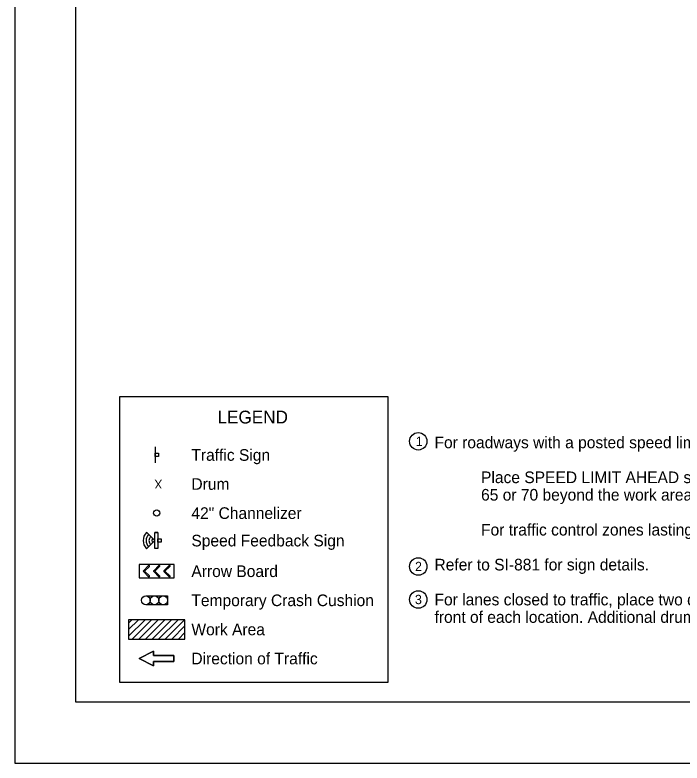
# Model space of a CAD drawing. Extents: x -2135039 to 114557, y -2139150 to -409929.
# Drawn here: x -2131439 to -2130293, y -2139150 to -2137865 of the extents above; entities that cross this region are included whole.
import ezdxf

# ---------------------------------------------------------------- set-up
doc = ezdxf.new("R2010")
doc.units = 0
for name, color, linetype in [('dsnDOTLogo', 7, 'Continuous'), ('dsnStdLabel', 7, 'Continuous'), ('dsnStdLineWork', 7, 'Continuous'), ('dsnStdNote', 7, 'Continuous'), ('Level 1', 7, 'Continuous'), ('Level 2', 7, 'Continuous'), ('StdNote', 7, 'Continuous')]:
    doc.layers.add(name, color=color, linetype=linetype)

msp = doc.modelspace()

# ---------------------------------------------------------------- linework, layer by layer
at = {"layer": 'dsnDOTLogo'}
msp.add_lwpolyline([(-2131438.9, -2139150.4), (-2128095, -2139150.4), (-2128095, -2136566.4), (-2131438.9, -2136566.4)], close=True, dxfattribs=at)
at = {"layer": 'dsnStdLabel'}
for p, q in [((-2131198, -2138607.5), (-2131198, -2138635)), ((-2131193.3, -2138754.5), (-2131193.3, -2138782)), ((-2131218.1, -2138820.1), (-2131209.3, -2138811.3)), ((-2131200.6, -2138820.1), (-2131191.8, -2138811.3)), ((-2131182.9, -2138820.1), (-2131174.1, -2138811.3)), ((-2131214.1, -2138863.4), (-2131176.6, -2138863.4)), ((-2131176.6, -2138863.4), (-2131176.6, -2138878.4)), ((-2131176.6, -2138878.4), (-2131214.1, -2138878.4)), ((-2131243.7, -2138909.9), (-2131238, -2138904.2)), ((-2131243.7, -2138921.2), (-2131226.7, -2138904.2)), ((-2131243.7, -2138932.5), (-2131215.4, -2138904.2)), ((-2131237.4, -2138937.5), (-2131204.1, -2138904.2)), ((-2131226.1, -2138937.5), (-2131192.8, -2138904.2)), ((-2131214.7, -2138937.5), (-2131181.5, -2138904.2)), ((-2131203.4, -2138937.5), (-2131170.1, -2138904.2)), ((-2131192.1, -2138937.5), (-2131158.8, -2138904.2)), ((-2131180.8, -2138937.5), (-2131147.5, -2138904.2)), ((-2131169.5, -2138937.5), (-2131147, -2138915)), ((-2131158.2, -2138937.5), (-2131147, -2138926.4))]:
    msp.add_line(p, q, dxfattribs=at)
for points in [[(-2131197.9, -2138623.9), (-2131197.9, -2138618.3), (-2131192.3, -2138618.3), (-2131192.3, -2138623.9)], [(-2131198.9, -2138782), (-2131198.9, -2138754.5), (-2131193.3, -2138754.5), (-2131193.3, -2138782)], [(-2131193.3, -2138771), (-2131193.3, -2138765.3), (-2131187.7, -2138765.3), (-2131187.7, -2138771)], [(-2131165.4, -2138809.4), (-2131225.4, -2138809.4), (-2131225.4, -2138832.3), (-2131165.4, -2138832.3)], [(-2131243.7, -2138904.2), (-2131243.7, -2138937.5), (-2131147, -2138937.5), (-2131147, -2138904.2)], [(-2131165.7, -2138965.9), (-2131165.7, -2138975.9), (-2131200.7, -2138975.9), (-2131200.7, -2138983.4), (-2131225.7, -2138970.9), (-2131200.7, -2138958.4), (-2131200.7, -2138965.9)]]:
    msp.add_lwpolyline(points, close=True, dxfattribs=at)
for points in [[(-2131209.3, -2138830.4), (-2131209.3, -2138830.4), (-2131218.1, -2138821.6), (-2131218.1, -2138821.6)], [(-2131207.9, -2138812.8), (-2131207.9, -2138812.8), (-2131216.4, -2138820.9), (-2131207.9, -2138828.9)], [(-2131191.8, -2138830.4), (-2131191.8, -2138830.4), (-2131200.6, -2138821.6), (-2131200.6, -2138821.6)], [(-2131190.3, -2138812.8), (-2131190.4, -2138812.8), (-2131198.8, -2138820.9), (-2131190.4, -2138828.9)], [(-2131174.1, -2138830.4), (-2131174.1, -2138830.4), (-2131183, -2138821.6), (-2131183, -2138821.6)], [(-2131172.7, -2138812.8), (-2131172.7, -2138812.8), (-2131181.2, -2138820.9), (-2131172.7, -2138828.9)], [(-2131200.7, -2138965.9), (-2131200.7, -2138958.4), (-2131225.7, -2138970.9), (-2131200.7, -2138983.4), (-2131200.7, -2138975.9), (-2131165.7, -2138975.9), (-2131165.7, -2138965.9), (-2131200.7, -2138965.9)]]:
    msp.add_lwpolyline(points, dxfattribs=at)
for centre, radius in [((-2131195.4, -2138721.1), 5.37), ((-2131195.4, -2138721.1), 5.37), ((-2131214.1, -2138870.9), 7.5), ((-2131214.1, -2138870.9), 7.5), ((-2131199.1, -2138870.9), 7.5), ((-2131199.1, -2138870.9), 7.5), ((-2131184.1, -2138870.9), 7.5), ((-2131184.1, -2138870.9), 7.5)]:
    msp.add_circle(centre, radius, dxfattribs=at)
for centre, start, end in [((-2131208.6, -2138812), 315.0975, 135.281), ((-2131191.1, -2138812), 315.0975, 135.281), ((-2131173.4, -2138812), 315.0975, 135.281), ((-2131217.4, -2138820.9), 134.1616, 224.6098), ((-2131199.9, -2138820.9), 134.1616, 224.6098), ((-2131182.2, -2138820.9), 134.1616, 224.6098), ((-2131208.6, -2138829.7), 226.201, 47.3602), ((-2131191.1, -2138829.7), 226.201, 47.3602), ((-2131173.4, -2138829.7), 226.201, 47.3602)]:
    msp.add_arc(centre, 1.03, start, end, dxfattribs=at)
at = {"layer": 'dsnStdLineWork'}
msp.add_lwpolyline([(-2131259.4, -2138521.1), (-2131259.4, -2139011.3), (-2130797.6, -2139011.3), (-2130797.6, -2138521.1), (-2131259.4, -2138521.1)], dxfattribs=at)
at = {"layer": 'dsnStdNote'}
for centre in [(-2130746, -2138597.7), (-2130746, -2138812.8), (-2130746, -2138869.5)]:
    msp.add_circle(centre, 15, dxfattribs=at)
at = {"layer": 'Level 1'}
msp.add_lwpolyline([(-2131334.4, -2137035.9), (-2128199.5, -2137035.9), (-2128199.5, -2139045.9), (-2131334.4, -2139045.9)], close=True, dxfattribs=at)
at = {"layer": 'Level 2'}
for p, q in [((-2131213, -2138754.1), (-2131198.9, -2138768.3)), ((-2131193.3, -2138754.5), (-2131198.9, -2138754.5)), ((-2131198.9, -2138768.3), (-2131213, -2138782.4)), ((-2131193.3, -2138782), (-2131198.9, -2138782))]:
    msp.add_line(p, q, dxfattribs=at)
for radius, start, end in [(20.3, 135.88, 224.0313), (15.3, 136.1665, 223.7159), (10.3, 136.7294, 223.0963), (5.32, 138.7005, 221.2995)]:
    msp.add_arc((-2131198.4, -2138768.3), radius, start, end, dxfattribs=at)

# ---------------------------------------------------------------- texts
at = {"layer": 'dsnStdLabel'}
for s, height, p in [('LEGEND', 22, (-2131090.9, -2138567.1)), ('Traffic Sign', 20, (-2131135.8, -2138631.2)), ('Drum', 20, (-2131135.8, -2138681.1)), ('42" Channelizer ', 20, (-2131135.8, -2138731.1)), ('Speed Feedback Sign', 20, (-2131135.8, -2138778.3)), ('Arrow Board', 20, (-2131135.8, -2138830.9)), ('Temporary Crash Cushion', 20, (-2131135.8, -2138880.9)), ('Work Area', 20, (-2131135.8, -2138930.9)), ('Direction of Traffic', 20, (-2131135.8, -2138980.9))]:
    msp.add_text(s, height=height, dxfattribs=at).set_placement(p)
msp.add_text('X', height=15, rotation=180, dxfattribs=at).set_placement((-2131185.9, -2138663.6))
at = {"layer": 'dsnStdNote'}
for s, p in [('1', (-2130750.2, -2138605.7)), ('2', (-2130751.6, -2138820.8)), ('3', (-2130751.7, -2138877.5))]:
    msp.add_text(s, height=16, dxfattribs=at).set_placement(p)
at = {"layer": 'StdNote'}
for s, p in [('For roadways with a posted speed limit of 60 mph or greater before road work:', (-2130718.1, -2138609.6)), ('Place SPEED LIMIT AHEAD sign and SPEED LIMIT 55 sign prior to the lane closure as shown. Place SPEED LIMIT', (-2130638.1, -2138669.6)), ('65 or 70 beyond the work area as shown.', (-2130638.1, -2138699.6)), ('For traffic control zones lasting more than 4 hours, place a Speed Feedback Sign at the end of the merge taper.', (-2130638.1, -2138759.6)), ('Refer to SI-881 for sign details.', (-2130718.1, -2138819.6)), ('For lanes closed to traffic, place two drums every 1000 feet. For full depth excavations in a closed lane, place two drums in ', (-2130718.1, -2138879.6)), ('front of each location. Additional drums need not be placed for full depth excavations spaced closer than 150 feet.', (-2130718.1, -2138909.6))]:
    msp.add_text(s, height=20, dxfattribs=at).set_placement(p)

doc.saveas('drawing.dxf')
